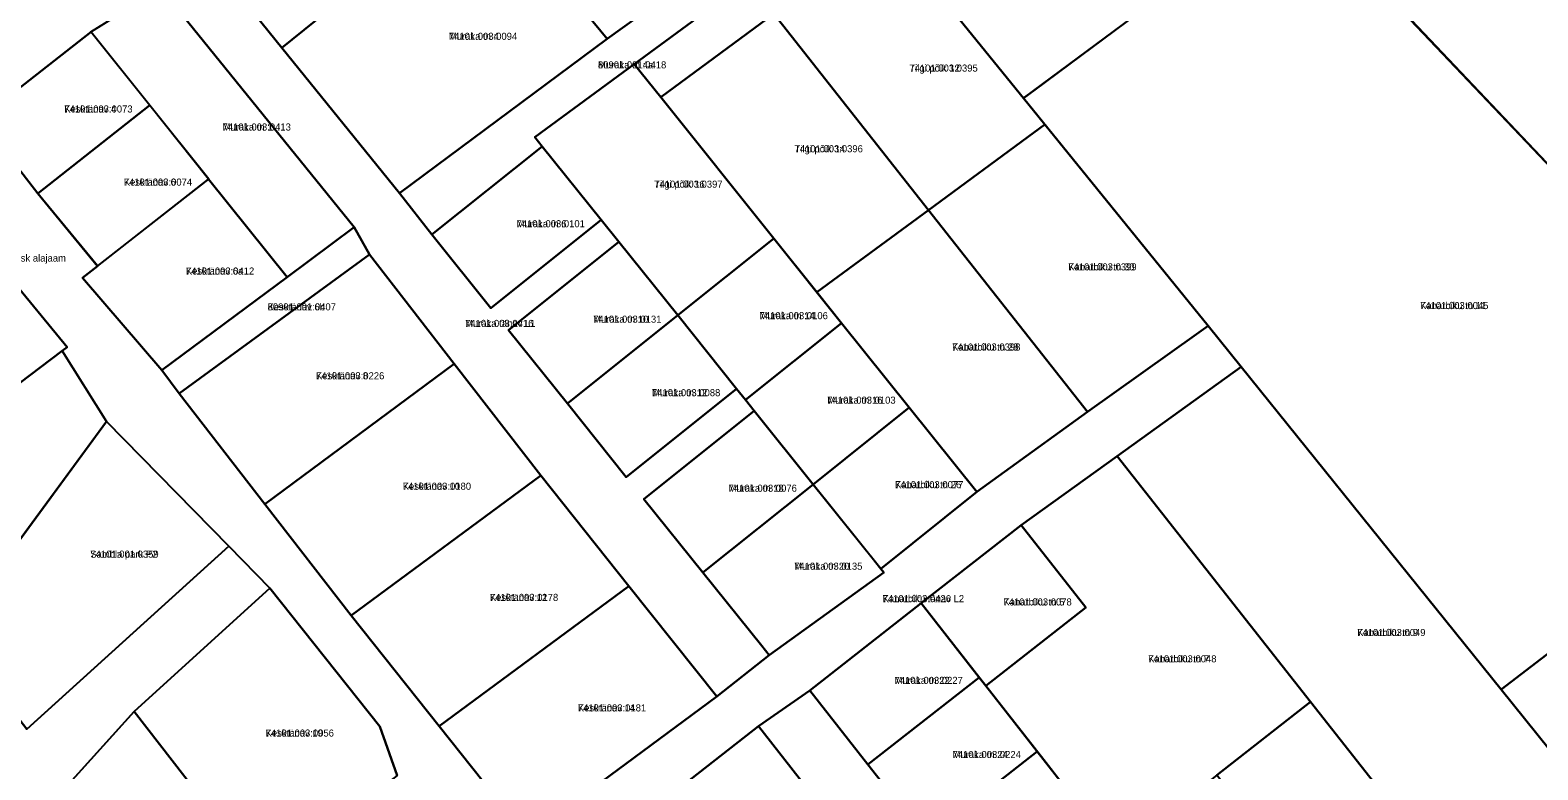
# Model space of a CAD drawing. Extents: x 524000 to 564260, y 6469338 to 6496391.
# Drawn here: x 538832.2 to 539152.2, y 6473497.9 to 6473655.1 of the extents above; entities that cross this region are included whole.
import ezdxf

# ---------------------------------------------------------------- set-up
doc = ezdxf.new("R2010")
doc.units = 0
for name, color, linetype in [('L_AADRESS', 7, 'Continuous'), ('PIIR', 7, 'Continuous'), ('TUNNUS', 7, 'Continuous')]:
    doc.layers.add(name, color=color, linetype=linetype)

msp = doc.modelspace()

# ---------------------------------------------------------------- linework, layer by layer
at = {"layer": 'PIIR'}
for points in [[(539005.29, 6474261.12), (539056.15, 6474208.49), (539096.96, 6474247.99), (539130.44, 6474280.39), (539213.84, 6474133.62), (539150.59, 6473967.33), (539206.6, 6473813.32), (539233.67, 6473543.12), (539211.42, 6473566.43), (539100.52, 6473683.3), (539094.55, 6473746.64), (539091.71, 6473754.61), (539088.7, 6473810.88), (539082.73, 6473838.08), (539070.81, 6473879.58), (539081.03, 6473887.43), (539069.97, 6473925.89), (538890.97, 6474150.36), (538914.51, 6474169.19), (538945.32, 6474197.72), (538967.17, 6474219.83), (538996.2, 6474251.02)], [(538943.08, 6473707.51), (538905.75, 6473754.62), (538925.56, 6473769.64), (538962.95, 6473722.6), (538995, 6473682.29), (538954.69, 6473653.23), (538928, 6473685.61), (538922.7, 6473692.04)], [(539056.85, 6473718.91), (539062.52, 6473711.91), (539038.34, 6473694.1), (539017.39, 6473678.66), (539014.17, 6473676.29), (539011.75, 6473674.51), (538990.07, 6473658.55), (538966.02, 6473640.83), (538960.39, 6473647.87), (538999.54, 6473676.7), (539011.9, 6473685.81)], [(538846.26, 6473711.4), (538866.56, 6473684.97), (538873.95, 6473675.34), (538869.28, 6473671.57), (538859.95, 6473664.03), (538845.12, 6473654.76), (538821.51, 6473636.25), (538818.36, 6473633.78), (538790.44, 6473668.85)], [(539038.34, 6473694.1), (539067.14, 6473658.54), (539045.45, 6473642.43), (539043.04, 6473640.64), (539014.17, 6473676.29), (539017.39, 6473678.66)], [(538873.05, 6473666.9), (538896.36, 6473685.76), (538908.94, 6473670.21), (538885.62, 6473651.35)], [(538908.94, 6473670.21), (538928, 6473685.61), (538954.69, 6473653.23), (538910.61, 6473620.45), (538885.62, 6473651.35)], [(539082.21, 6473592.27), (539043.04, 6473640.64), (539100.6, 6473683.38), (539211.42, 6473566.43), (539144.4, 6473515.04), (539089.25, 6473583.53)], [(538995, 6473682.29), (538999.54, 6473676.7), (538960.39, 6473647.87), (538939.32, 6473632.35), (538940.88, 6473630.4), (538917.47, 6473611.64), (538910.61, 6473620.45), (538954.69, 6473653.23)], [(539014.17, 6473676.29), (539043.04, 6473640.64), (539047.56, 6473635.06), (539045.15, 6473633.28), (539022.86, 6473616.87), (538990.07, 6473658.55), (539011.75, 6473674.51)], [(538859.92, 6473663.97), (538900.95, 6473613.21), (538886.74, 6473602.64), (538870.06, 6473623.44), (538857.57, 6473639.06), (538845.08, 6473654.7)], [(538990.07, 6473658.55), (539022.86, 6473616.87), (538999.14, 6473599.41), (538990.01, 6473610.82), (538966.02, 6473640.83)], [(538821.51, 6473636.25), (538845.12, 6473654.76), (538857.6, 6473639.13), (538833.78, 6473620.41)], [(538966.02, 6473640.83), (538990.01, 6473610.82), (538969.64, 6473594.5), (538957.14, 6473610.11), (538953.39, 6473614.79), (538940.88, 6473630.4), (538939.32, 6473632.35), (538960.39, 6473647.87)], [(538833.78, 6473620.41), (538857.6, 6473639.13), (538870.08, 6473623.5), (538846.47, 6473604.99)], [(539047.56, 6473635.06), (539082.21, 6473592.27), (539079.77, 6473590.52), (539056.61, 6473573.98), (539022.86, 6473616.87), (539045.15, 6473633.28)], [(538917.47, 6473611.64), (538940.88, 6473630.4), (538953.39, 6473614.79), (538929.98, 6473596.03)], [(538870.06, 6473623.44), (538886.74, 6473602.64), (538860.15, 6473582.87), (538843.3, 6473602.49), (538846.45, 6473604.93)], [(539022.86, 6473616.87), (539056.61, 6473573.98), (539033.15, 6473556.97), (539018.76, 6473574.91), (539004.38, 6473592.86), (538999.14, 6473599.41)], [(538904.22, 6473607.41), (538863.79, 6473577.89), (538860.15, 6473582.87), (538886.74, 6473602.64), (538900.95, 6473613.21)], [(538933.72, 6473591.36), (538957.14, 6473610.11), (538969.64, 6473594.5), (538946.22, 6473575.75)], [(538969.64, 6473594.5), (538990.01, 6473610.82), (539004.38, 6473592.86), (538984.01, 6473576.54), (538982.14, 6473578.89)], [(538863.79, 6473577.89), (538904.22, 6473607.41), (538922.21, 6473584.17), (538881.97, 6473554.41)], [(538789.71, 6473574.75), (538803.43, 6473585.12), (538813.64, 6473592.76), (538827.37, 6473603.16), (538840.03, 6473587.73), (538838.99, 6473586.95), (538816.09, 6473569.65), (538798.14, 6473563.58)], [(538946.22, 6473575.75), (538969.64, 6473594.5), (538982.14, 6473578.89), (538958.72, 6473560.14)], [(538984.01, 6473576.54), (539004.38, 6473592.86), (539018.76, 6473574.91), (538998.39, 6473558.59), (538985.89, 6473574.2)], [(539082.21, 6473592.27), (539089.25, 6473583.53), (539062.91, 6473564.58), (539042.54, 6473549.92), (539021.31, 6473533.32), (538997.68, 6473514.83), (538986.76, 6473507.2), (538966.28, 6473491.18), (538945.42, 6473474.85), (538937.65, 6473483.72), (538977.91, 6473513.5), (538989.08, 6473522.31), (539013.41, 6473539.87), (539012.78, 6473540.65), (539033.15, 6473556.97), (539056.61, 6473573.98), (539079.77, 6473590.52)], [(538848.4, 6473571.92), (538801.98, 6473508.7), (538799.8, 6473511.58), (538789.86, 6473524.75), (538777.82, 6473540.71), (538798.14, 6473563.58), (538816.09, 6473569.65), (538838.99, 6473586.95)], [(538881.97, 6473554.41), (538922.21, 6473584.17), (538940.56, 6473560.45), (538900.33, 6473530.7)], [(539144.4, 6473515.04), (539164.83, 6473489.68), (539137.18, 6473470.18), (539129.15, 6473480.37), (539103.98, 6473512.36), (539062.91, 6473564.58), (539089.25, 6473583.53)], [(538962.47, 6473555.45), (538985.89, 6473574.2), (538998.39, 6473558.59), (538974.97, 6473539.84)], [(538998.39, 6473558.59), (539018.76, 6473574.91), (539033.15, 6473556.97), (539012.78, 6473540.65)], [(538831.5, 6473506.61), (538815.58, 6473527.22), (538848.4, 6473571.92), (538874.33, 6473545.46)], [(539103.98, 6473512.36), (539084.1, 6473496.79), (539062.88, 6473480.18), (539051.05, 6473495.32), (539047.35, 6473500.05), (539035.02, 6473515.8), (539056.25, 6473532.4), (539042.54, 6473549.92), (539062.91, 6473564.58)], [(539233.67, 6473543.12), (539250.35, 6473373.95), (539223.86, 6473414.2), (539217.2, 6473423.71), (539164.83, 6473489.68), (539144.4, 6473515.04), (539211.42, 6473566.43)], [(538900.33, 6473530.7), (538940.56, 6473560.45), (538959.23, 6473536.98), (538918.99, 6473507.21)], [(538987.51, 6473524.26), (538974.97, 6473539.84), (538998.39, 6473558.59), (539010.91, 6473542.99), (539012.78, 6473540.65), (539013.41, 6473539.87), (538989.08, 6473522.31)], [(539021.31, 6473533.32), (539042.54, 6473549.92), (539056.25, 6473532.4), (539035.02, 6473515.8)], [(538874.33, 6473545.46), (538883.08, 6473536.52), (538854.24, 6473510.36), (538840.44, 6473495.03), (538816.26, 6473477.19), (538801.85, 6473465.94), (538760.64, 6473420.14), (538745.93, 6473401.69), (538729.29, 6473380.83), (538718, 6473394.65), (538732.82, 6473416.15), (538732.08, 6473417.02), (538750.86, 6473441.68), (538751.83, 6473440.29), (538772.8, 6473468.56), (538782.98, 6473484.33), (538801.98, 6473508.7), (538815.58, 6473527.22), (538831.5, 6473506.61)], [(538906.42, 6473507.17), (538910.07, 6473496.74), (538903.58, 6473491.73), (538905.87, 6473488.76), (538883.99, 6473471.98), (538878.96, 6473478.47), (538854.24, 6473510.36), (538883.08, 6473536.52)], [(538918.99, 6473507.21), (538959.23, 6473536.98), (538977.91, 6473513.5), (538937.65, 6473483.72)], [(538997.68, 6473514.83), (539021.31, 6473533.32), (539033.63, 6473517.57), (539010.01, 6473499.08)], [(539010.01, 6473499.08), (539033.63, 6473517.57), (539035.02, 6473515.8), (539045.96, 6473501.82), (539022.34, 6473483.33)], [(538852.18, 6473479.83), (538840.44, 6473495.03), (538854.24, 6473510.36), (538875.28, 6473483.21), (538864.96, 6473475.26), (538857.56, 6473484.31)], [(539129.15, 6473480.37), (539109.64, 6473465.11), (539104.59, 6473470.61), (539084.1, 6473496.79), (539103.98, 6473512.36)], [(538966.28, 6473491.18), (538986.76, 6473507.2), (539000.98, 6473489.02), (538980.5, 6473473)]]:
    msp.add_lwpolyline(points, close=True, dxfattribs=at)
for points in [[(538790.44, 6473668.85), (538818.36, 6473633.78), (538821.51, 6473636.25), (538833.78, 6473620.41), (538846.45, 6473604.93), (538843.3, 6473602.49), (538860.15, 6473582.87), (538863.79, 6473577.89), (538881.97, 6473554.41), (538900.33, 6473530.7), (538918.99, 6473507.21), (538937.65, 6473483.72), (538945.42, 6473474.85), (538974.45, 6473438.22), (538987.99, 6473421.14), (539019.92, 6473380.27), (539033.35, 6473363.32), (539046.78, 6473346.15), (539060.21, 6473328.98), (539073.64, 6473311.81), (539082.11, 6473303.28), (539135.86, 6473234.01), (539149.77, 6473216.07), (539153.84, 6473218.89)], [(538873.05, 6473666.9), (538885.62, 6473651.35), (538910.61, 6473620.45), (538917.47, 6473611.64), (538929.98, 6473596.03), (538953.39, 6473614.79), (538957.14, 6473610.11), (538933.72, 6473591.36), (538946.22, 6473575.75), (538958.72, 6473560.14), (538982.14, 6473578.89), (538984.01, 6473576.54), (538985.89, 6473574.2), (538962.47, 6473555.45), (538974.97, 6473539.84), (538987.51, 6473524.26), (538989.08, 6473522.31), (538977.91, 6473513.5), (538959.23, 6473536.98), (538940.56, 6473560.45), (538922.21, 6473584.17), (538904.22, 6473607.41), (538900.95, 6473613.21), (538859.92, 6473663.97)], [(538910.07, 6473496.74), (538906.42, 6473507.17), (538883.08, 6473536.52), (538874.33, 6473545.46), (538848.4, 6473571.92), (538838.99, 6473586.95), (538840.03, 6473587.73), (538827.37, 6473603.16)], [(539000.98, 6473489.02), (538986.76, 6473507.2), (538997.68, 6473514.83), (539010.01, 6473499.08), (539022.34, 6473483.33), (539045.96, 6473501.82), (539051.05, 6473495.32)]]:
    msp.add_lwpolyline(points, dxfattribs=at)

# ---------------------------------------------------------------- texts
at = {"layer": 'L_AADRESS'}
for s, p in [('Muraka tn 4', (538921.06, 6473653.03)), ('Muraka tn 4a', (538952.71, 6473646.96)), ('Tiigi põik 12', (539018.82, 6473646.28)), ('Kesktänav 4', (538839.42, 6473637.59)), ('Muraka tn 1', (538873.02, 6473633.76)), ('Tiigi põik 14', (538994.44, 6473629.14)), ('Kesktänav 6', (538852.06, 6473622.06)), ('Tiigi põik 16', (538964.66, 6473621.62)), ('Muraka tn 6', (538935.43, 6473613.21)), ('Kesktänav 9 // Kesk alajaam', (538814.46, 6473605.92)), ('Kesktänav 6a', (538865.24, 6473603.16)), ('Kanarbiku tn 30', (539052.54, 6473604.04)), ('Kesktänav 6b', (538882.59, 6473595.55)), ('Kanarbiku tn 11', (539127.23, 6473595.82)), ('Muraka tänav L1', (538924.5, 6473592.04)), ('Muraka tn 10', (538951.68, 6473592.93)), ('Muraka tn 14', (538987.01, 6473593.68)), ('Kanarbiku tn 28', (539027.88, 6473587.02)), ('Kesktänav 8', (538892.86, 6473580.91)), ('Muraka tn 12', (538964.18, 6473577.32)), ('Muraka tn 16', (539001.39, 6473575.73)), ('Kesktänav 10', (538911.27, 6473557.44)), ('Muraka tn 18', (538980.43, 6473557.02)), ('Kanarbiku tn 26', (539015.77, 6473557.78)), ('Sambla park P2', (538844.95, 6473543.02)), ('Muraka tn 20', (538994.34, 6473540.45)), ('Kesktänav 12', (538929.77, 6473533.83)), ('Kanarbiku tänav L2', (539013.14, 6473533.56)), ('Kanarbiku tn 5', (539038.78, 6473532.86)), ('Kanarbiku tn 9', (539113.87, 6473526.37)), ('Kanarbiku tn 7', (539069.5, 6473520.78)), ('Muraka tn 22', (539015.66, 6473516.2)), ('Kesktänav 14', (538948.44, 6473510.35)), ('Kesktänav 19', (538882.16, 6473505.01)), ('Muraka tn 24', (539027.98, 6473500.45))]:
    msp.add_text(s, height=1.5, dxfattribs=at).set_placement(p)
at = {"layer": 'TUNNUS'}
for s, p in [('74101:003:0094', (538921.06, 6473653.03)), ('80901:001:0418', (538952.71, 6473646.96)), ('74101:003:0395', (539018.82, 6473646.28)), ('74101:003:0073', (538839.42, 6473637.59)), ('74101:003:0413', (538873.02, 6473633.76)), ('74101:003:0396', (538994.44, 6473629.14)), ('74101:003:0074', (538852.06, 6473622.06)), ('74101:003:0397', (538964.66, 6473621.62)), ('74101:003:0101', (538935.43, 6473613.21)), ('74101:003:0412', (538865.24, 6473603.16)), ('74101:003:0399', (539052.54, 6473604.04)), ('80901:001:0407', (538882.59, 6473595.55)), ('74101:003:0045', (539127.23, 6473595.82)), ('74101:003:0416', (538924.5, 6473592.04)), ('74101:003:0131', (538951.68, 6473592.93)), ('74101:003:0106', (538987.01, 6473593.68)), ('74101:003:0398', (539027.88, 6473587.02)), ('74101:003:0226', (538892.86, 6473580.91)), ('74101:003:0088', (538964.18, 6473577.32)), ('74101:003:0103', (539001.39, 6473575.73)), ('74101:003:0180', (538911.27, 6473557.44)), ('74101:003:0076', (538980.43, 6473557.02)), ('74101:003:0077', (539015.77, 6473557.78)), ('74101:001:0359', (538844.95, 6473543.02)), ('74101:003:0135', (538994.34, 6473540.45)), ('74101:003:0178', (538929.77, 6473533.83)), ('74101:003:0426', (539013.14, 6473533.56)), ('74101:003:0078', (539038.78, 6473532.86)), ('74101:003:0049', (539113.87, 6473526.37)), ('74101:003:0048', (539069.5, 6473520.78)), ('74101:003:0227', (539015.66, 6473516.2)), ('74101:003:0181', (538948.44, 6473510.35)), ('74101:003:0056', (538882.16, 6473505.01)), ('74101:003:0224', (539027.98, 6473500.45))]:
    msp.add_text(s, height=1.5, dxfattribs=at).set_placement(p)

doc.saveas('drawing.dxf')
